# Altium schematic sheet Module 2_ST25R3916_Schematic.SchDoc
size A4; DocumentNumber: 4; SheetNumber: 4; SheetTotal: 5; PageSetup: Record=PageOptions¦CenterHorizontal=True¦CenterVertical=True¦PrintScale=0.97¦XCorrection=1.00¦YCorrection=1.00¦PrintKind=0¦BorderSize=5000000¦LeftOffset=0¦BottomOffset=0¦Orientation=2¦PaperLength=1000¦PaperWidth=1000¦Scale=100¦PaperSource=7¦PrintQuality=-4¦MediaType=1¦DitherType=10¦PaperKind=A4¦PrintScaleMode=1
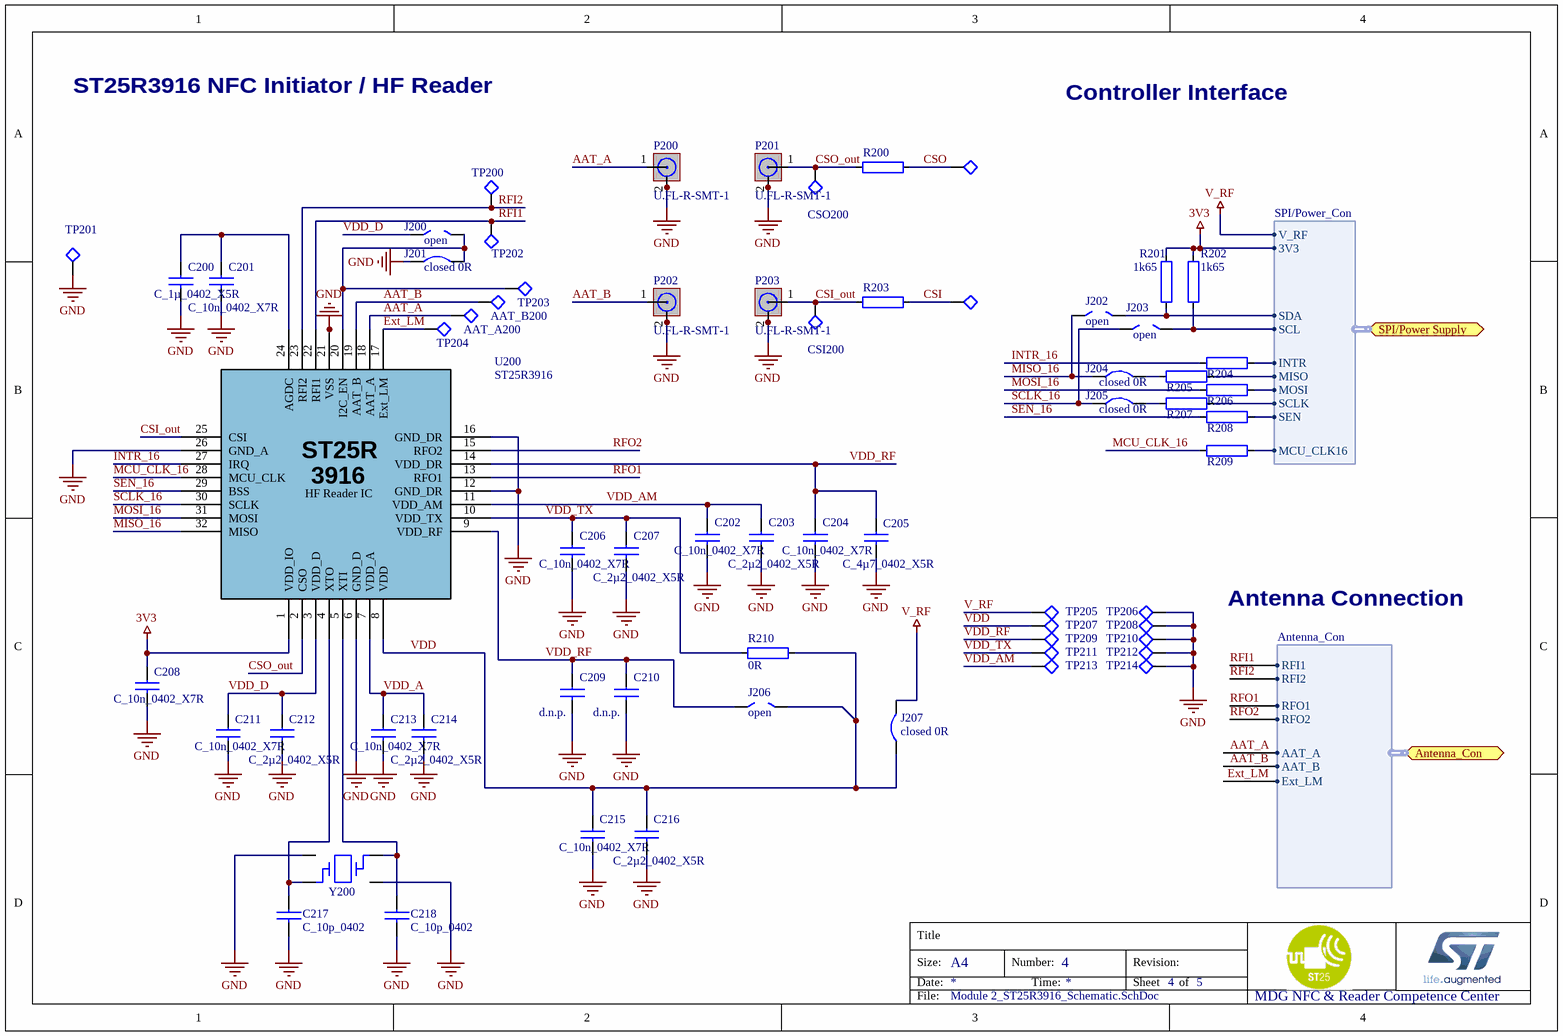
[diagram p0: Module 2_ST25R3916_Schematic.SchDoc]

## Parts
AAT_A200  *  [TP_0.5]  (value not drawn)  (no BOM)
AAT_B200  *  [TP_0.5]  (value not drawn)  (no BOM)
C200  C_1µ_0402_X5R  [C0402]
C201  C_10n_0402_X7R  [C0402]
C202  C_10n_0402_X7R  [C0402]
C203  C_2µ2_0402_X5R  [C0402]
C204  C_10n_0402_X7R  [C0402]
C205  C_4µ7_0402_X5R  [C0402]
C206  C_10n_0402_X7R  [C0402]
C207  C_2µ2_0402_X5R  [C0402]
C208  C_10n_0402_X7R  [C0402]
C209  d.n.p.  [C0402]
C210  d.n.p.  [C0402]
C211  C_10n_0402_X7R  [C0402]
C212  C_2µ2_0402_X5R  [C0402]
C213  C_10n_0402_X7R  [C0402]
C214  C_2µ2_0402_X5R  [C0402]
C215  C_10n_0402_X7R  [C0402]
C216  C_2µ2_0402_X5R  [C0402]
C217  C_10p_0402  [C0402]
C218  C_10p_0402  [C0402]
CP200  CS1  [Capacitive_plate]  (value not drawn)  (no BOM)
CP201  CS1  [Capacitive_plate]  (value not drawn)  (no BOM)
CSI200  *  [TP_0.5]  (value not drawn)  (no BOM)
CSO200  *  [TP_0.5]  (value not drawn)  (no BOM)
J200  open  [JP2_SMD_open_0402]  (net tie, no BOM)
J201  closed 0R  [JP2_SMD_closed_0402]  (net tie)
J202  open  [JP2_SMD_open_0402]  (net tie, no BOM)
J203  open  [JP2_SMD_open_0402]  (net tie, no BOM)
J204  closed 0R  [JP2_SMD_closed_0402]  (net tie)
J205  closed 0R  [JP2_SMD_closed_0402]  (net tie)
J206  open  [JP2_SMD_open_0402]  (net tie, no BOM)
J207  closed 0R  [JP2_SMD_closed]  (net tie)
P200  U.FL-R-SMT-1  [U FL Socket - HRS - Surface Mount]
P201  U.FL-R-SMT-1  [U FL Socket - HRS - Surface Mount]
P202  U.FL-R-SMT-1  [U FL Socket - HRS - Surface Mount]
P203  U.FL-R-SMT-1  [U FL Socket - HRS - Surface Mount]
R200  50R  [R0402]  (value not drawn)
R201  1k65  [R0402]
R202  1k65  [R0402]
R203  50R  [R0402]  (value not drawn)
R204  0R  [R0402]  (value not drawn)
R205  0R  [R0402]  (value not drawn)
R206  0R  [R0402]  (value not drawn)
R207  0R  [R0402]  (value not drawn)
R208  0R  [R0402]  (value not drawn)
R209  0R  [R0402]  (value not drawn)
R210  0R  [R0402]
TP200  *  [TP_0.5]  (value not drawn)  (no BOM)
TP201  d.n.p.  [1*1P_MALE]  (value not drawn)  (no BOM)
TP202  *  [TP_0.5]  (value not drawn)  (no BOM)
TP203  *  [TP_0.5]  (value not drawn)  (no BOM)
TP204  *  [TP_0.5]  (value not drawn)  (no BOM)
TP205  d.n.p.  [TP_1mm]  (value not drawn)  (no BOM)
TP206  d.n.p.  [TP_1mm]  (value not drawn)  (no BOM)
TP207  d.n.p.  [TP_1mm]  (value not drawn)  (no BOM)
TP208  d.n.p.  [TP_1mm]  (value not drawn)  (no BOM)
TP209  d.n.p.  [TP_1mm]  (value not drawn)  (no BOM)
TP210  d.n.p.  [TP_1mm]  (value not drawn)  (no BOM)
TP211  d.n.p.  [TP_1mm]  (value not drawn)  (no BOM)
TP212  d.n.p.  [TP_1mm]  (value not drawn)  (no BOM)
TP213  d.n.p.  [TP_1mm]  (value not drawn)  (no BOM)
TP214  d.n.p.  [TP_1mm]  (value not drawn)  (no BOM)
U200  ST25R3916  [ST25R3916-QFN32_5X5_0.5]
Y200  NDK 27,12MHz Crystal  [XRCGB_F_MN]  (value not drawn)

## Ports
Antenna_Con (harness Antenna_Con), SPI/Power Supply (harness SPI/Power_Con)

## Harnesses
Antenna_Con: RFI1, RFI2, RFO1, RFO2, AAT_A, AAT_B, Ext_LM
SPI/Power_Con: SEN, INTR, MISO, MOSI, SCLK, V_RF, 3V3, SDA, SCL, MCU_CLK16

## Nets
3V3: C208.1 R201.2 R202.2 U200.1(VDD_IO) ; port SPI/Power Supply.3V3
GND: C200.2 C201.2 C202.2 C203.2 C204.2 C205.2 C206.2 C207.2 C208.2 C209.2 C210.2 C211.2 C212.2 C213.2 C214.2 C215.2 C216.2 C217.2 C218.2 J201.1 P200.2 P200.3 P201.2 P201.3 P202.2 P202.3 P203.2 P203.3 TP201.1 TP206.1 TP208.1 TP210.1 TP212.1 TP214.1 U200.6(GND_D) U200.12(GND_DR) U200.16(GND_DR) U200.21(VSS) U200.26(GND_A) U200.33(VSS) Y200.2 Y200.4
V_RF: J207.2 TP205.1 ; port SPI/Power Supply.V_RF
AAT_A: AAT_A200.1 P200.1 U200.18(AAT_A) ; port Antenna_Con.AAT_A
AAT_B: AAT_B200.1 P202.1 U200.19(AAT_B) ; port Antenna_Con.AAT_B
CSI: CP201.1 R203.1
CSI_out: CSI200.1 P203.1 R203.2 U200.25(CSI)
CSO: CP200.1 R200.1
CSO_out: CSO200.1 P201.1 R200.2 U200.2(CSO)
Ext_LM: TP204.1 U200.17(Ext_LM) ; port Antenna_Con.Ext_LM
INTR_16: R204.2 U200.27(IRQ)
MCU_CLK_16: R209.2 U200.28(MCU_CLK)
MISO_16: J202.1 J204.1 U200.32(MISO)
MOSI_16: R206.2 U200.31(MOSI)
RFI1: TP202.1 U200.22(RFI1) ; port Antenna_Con.RFI1
RFI2: TP200.1 U200.23(RFI2) ; port Antenna_Con.RFI2
RFO1: U200.13(RFO1) ; port Antenna_Con.RFO1
RFO2: U200.15(RFO2) ; port Antenna_Con.RFO2
SCLK_16: J203.1 J205.1 U200.30(SCLK)
SEN_16: R208.2 U200.29(BSS)
VDD: C215.1 C216.1 J206.2 J207.1 R210.1 TP207.1 U200.8(VDD)
VDD_A: C213.1 C214.1 U200.7(VDD_A)
VDD_AM: C202.1 C203.1 TP213.1 U200.11(VDD_AM)
VDD_D: C211.1 C212.1 J200.1 U200.3(VDD_D)
VDD_RF: C204.1 C205.1 C209.1 C210.1 J206.1 TP209.1 U200.9(VDD_RF) U200.14(VDD_DR)
VDD_TX: C206.1 C207.1 R210.2 TP211.1 U200.10(VDD_TX)
NetC200_1: C200.1 C201.1 U200.24(AGDC)
NetC217_1: C217.1 U200.4(XTO) Y200.3
NetC218_1: C218.1 U200.5(XTI) Y200.1
NetJ200_2: J200.2 J201.2 TP203.1 U200.20(I2C_EN)
NetJ202_2: J202.2 R201.1 ; port SPI/Power Supply.SDA
NetJ203_2: J203.2 R202.1 ; port SPI/Power Supply.SCL
NetJ204_2: J204.2 R205.2
NetJ205_2: J205.2 R207.2
NetR204_1: R204.1 ; port SPI/Power Supply.INTR
NetR205_1: R205.1 ; port SPI/Power Supply.MISO
NetR206_1: R206.1 ; port SPI/Power Supply.MOSI
NetR207_1: R207.1 ; port SPI/Power Supply.SCLK
NetR208_1: R208.1 ; port SPI/Power Supply.SEN
NetR209_1: R209.1 ; port SPI/Power Supply.MCU_CLK16

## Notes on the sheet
- ST25R3916 NFC Initiator / HF Reader
- Controller Interface
- Antenna Connection

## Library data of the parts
AAT_A200 AAT_B200 CSI200 CSO200 TP200-TP214 = Test point 0.5mm
C200 = C_1µ_0402_X5R: 1u_X5R; Manufacturer: MURATA; Manufacturer Part Number: GRM155R61C105KA12D; 2nd Source: 0402, 1 µF, 16 V, ± 10%, X5R,
C201 C202 C204 C206 C208 C211 C213 C215 = C_10n_0402_X7R: 10n_x7R; Manufacturer: AVX; Manufacturer Part Number: 04023C103KAT2A; 2nd Source: 0402, 0.01 µF, 25 V, ± 10%, X7R
C203 C207 C212 C214 C216 = C_2µ2_0402_X5R: 2u2_X5R; Manufacturer: MURATA; Manufacturer Part Number: GRM155R60J225ME15D; 2nd Source: 0402, 2.2 µF, 6.3 V, ± 20%, X5R
C205 = C_4µ7_0402_X5R: 4u7_X5R; Manufacturer: TDK; Manufacturer Part Number: C1005X5R0J475K050BC; 2nd Source: 0402, 4.7 µF, 6.3 V, ± 10%, X5R
C209 = C_10n_0402_X7R: Manufacturer: AVX; Manufacturer Part Number: 04023C103KAT2A; 2nd Source: 0402, 0.01 µF, 25 V, ± 10%, X7R
C210 = C_2µ2_0402_X5R: Manufacturer: MURATA; Manufacturer Part Number: GRM155R60J225ME15D; 2nd Source: 0402, 2.2 µF, 6.3 V, ± 20%, X5R
C217 C218 = C_10p_0402: 10p_COG; Manufacturer: MURATA; Manufacturer Part Number: GRM1555C1H100GA01D; 2nd Source: 10pF ±2% 50V  C0G, NP0 0402
CP200 CP201 = Capacitive_plate: Capacitive Sensing
J200 J202 J203 J206 = solder_jumper_open_0402
J201 J204 J205 = solder_jumper_closed_0402: 0R; Manufacturer: Multicomp; Manufacturer Part Number: MC00625W040210R
J207 = solder_jumper_closed: 0R; Manufacturer: Multicomp; Manufacturer Part Number: MC00625W040210R
P200-P203 = U.FL-R-SMT-1: Manufacturer: HIROSE(HRS); Manufacturer Part Number: U.FL-R-SMT-1(10); 2nd Source: yes
R200 R203 = R0402_50R: 50R, 0402; Manufacturer: MULTICOMP; Manufacturer Part Number: MCMR04X49R9FTL; 2nd Source: 49.9 ohm, 50 V, 0402, >62.5 mW, ± 1%
R201 R202 = R0402_1k65: 1k65, 0402; Manufacturer: MULTICOMP; Manufacturer Part Number: MC00625W040211K65; 2nd Source: 1.65 kohm, 50 V, 0402, >62.5 mW, ± 1%
R204-R210 = R0402_0R: 0R, 0402; Manufacturer: MULTICOMP; Manufacturer Part Number: MC00625W040210R; 2nd Source: 0 ohm, 50 V, 0402, >62.5 mW
U200 = ST25R3916: NFC Initiator / HF Reader IC; Manufacturer: STMicroelectronics; Manufacturer Part Number: ST25R3916-AQFMCT-ND
Y200 = NDK NX2016SA: NDK NX2016SA 27.12MHz; Manufacturer: MURATA; Manufacturer Part Number: NX2016SA STD-CZS-5 27.12MHz; 2nd Source: Murata XRCGB27M120F3M00R0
